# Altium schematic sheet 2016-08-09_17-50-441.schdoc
size 349 x 127 mm; SheetNumber: 1; SheetTotal: 1
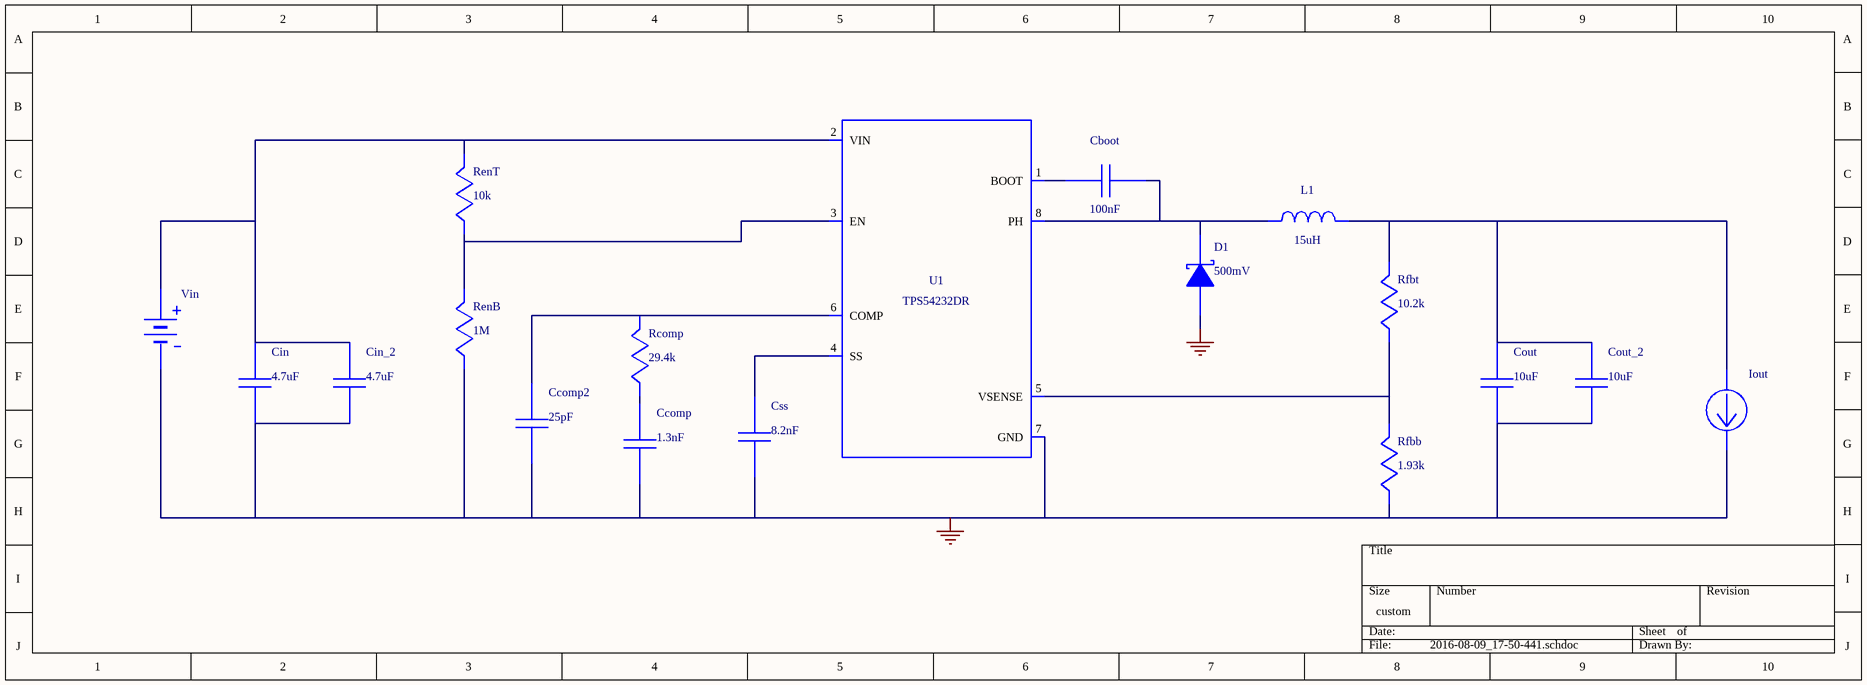
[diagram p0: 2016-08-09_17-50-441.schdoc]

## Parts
Cboot  value 100nF  (hidden comment: GRM155R61A104KA01D)
Ccomp  value 1.3nF  (hidden comment: GRM2165C2A132JA01D)
Ccomp2  value 25pF  (hidden comment: CL21C250JBANNNC)
Cin  value 4.7uF  (hidden comment: GRM32ER71H475KA88L)
Cin_2  value 4.7uF  (hidden comment: GRM32ER71H475KA88L)
Cout  value 10uF  (hidden comment: GRM219R61A106KE44D)
Cout_2  value 10uF  (hidden comment: GRM219R61A106KE44D)
Css  value 8.2nF  (hidden comment: GRM033R61A822KA01D)
D1  value 500mV  (hidden comment: B240A-13-F)
Iout  WB_CURRENT_LOAD  (value not drawn)
L1  value 15uH  (hidden comment: SRN6045-150M)
Rcomp  value 29.4k  (hidden comment: CRCW040229K4FKED)
RenB  value 1M  (hidden comment: CRCW04021M00FKED)
RenT  value 10k  (hidden comment: CRCW040210K0FKED)
Rfbb  value 1.93k  (hidden comment: RT0805BRD071K93L)
Rfbt  value 10.2k  (hidden comment: CRCW040210K2FKED)
U1  TPS54231DR  (value not drawn)
Vin  WB_BATTERY  (value not drawn)

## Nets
0: Ccomp.2 Ccomp2.2 Cin.2 Cin_2.2 Cout.2 Cout_2.2 Css.2 D1.2(A) Iout.2(-) RenB.2 Rfbb.2 U1.7(GND) Vin.2(-)
NetCboot_1: Cboot.1 U1.1(BOOT)
NetCboot_2: Cboot.2 D1.1(K) L1.2 U1.8(PH)
NetCcomp2_1: Ccomp2.1 Rcomp.1 U1.6(COMP)
NetCcomp_1: Ccomp.1 Rcomp.2
NetCin_1: Cin.1 Cin_2.1 RenT.1 U1.2(VIN) Vin.1(+)
NetCout_1: Cout.1 Cout_2.1 Iout.1(+) L1.1 Rfbt.1
NetCss_1: Css.1 U1.4(SS)
NetRenB_1: RenB.1 RenT.2 U1.3(EN)
NetRfbb_1: Rfbb.1 Rfbt.2 U1.5(VSENSE)

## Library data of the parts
Cboot = GRM155R61A104KA01D: GRM155R61A104KA0; Manufacturer Name: MuRata
Ccomp = GRM2165C2A132JA01D: GRM2165C2A132JA0; Manufacturer Name: MuRata
Ccomp2 = CL21C250JBANNNC: Manufacturer Name: Samsung Electro-Mechanics
Cin Cin_2 = GRM32ER71H475KA88L: GRM32ER71H475KA8; Manufacturer Name: MuRata
Cout Cout_2 = GRM219R61A106KE44D: GRM219R61A106KE4; Manufacturer Name: MuRata
Css = GRM033R61A822KA01D: GRM033R61A822KA0; Manufacturer Name: MuRata
D1 = B240A-13-F: Manufacturer Name: Diodes Inc.
L1 = SRN6045-150M: Manufacturer Name: Bourns
Rcomp = CRCW040229K4FKED: Manufacturer Name: Vishay-Dale
RenB = CRCW04021M00FKED: Manufacturer Name: Vishay-Dale
RenT = CRCW040210K0FKED: Manufacturer Name: Vishay-Dale
Rfbb = RT0805BRD071K93L: Manufacturer Name: Yageo America
Rfbt = CRCW040210K2FKED: Manufacturer Name: Vishay-Dale
U1 = TPS54231DR: TPS54232DR; Manufacturer Name: Texas Instruments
